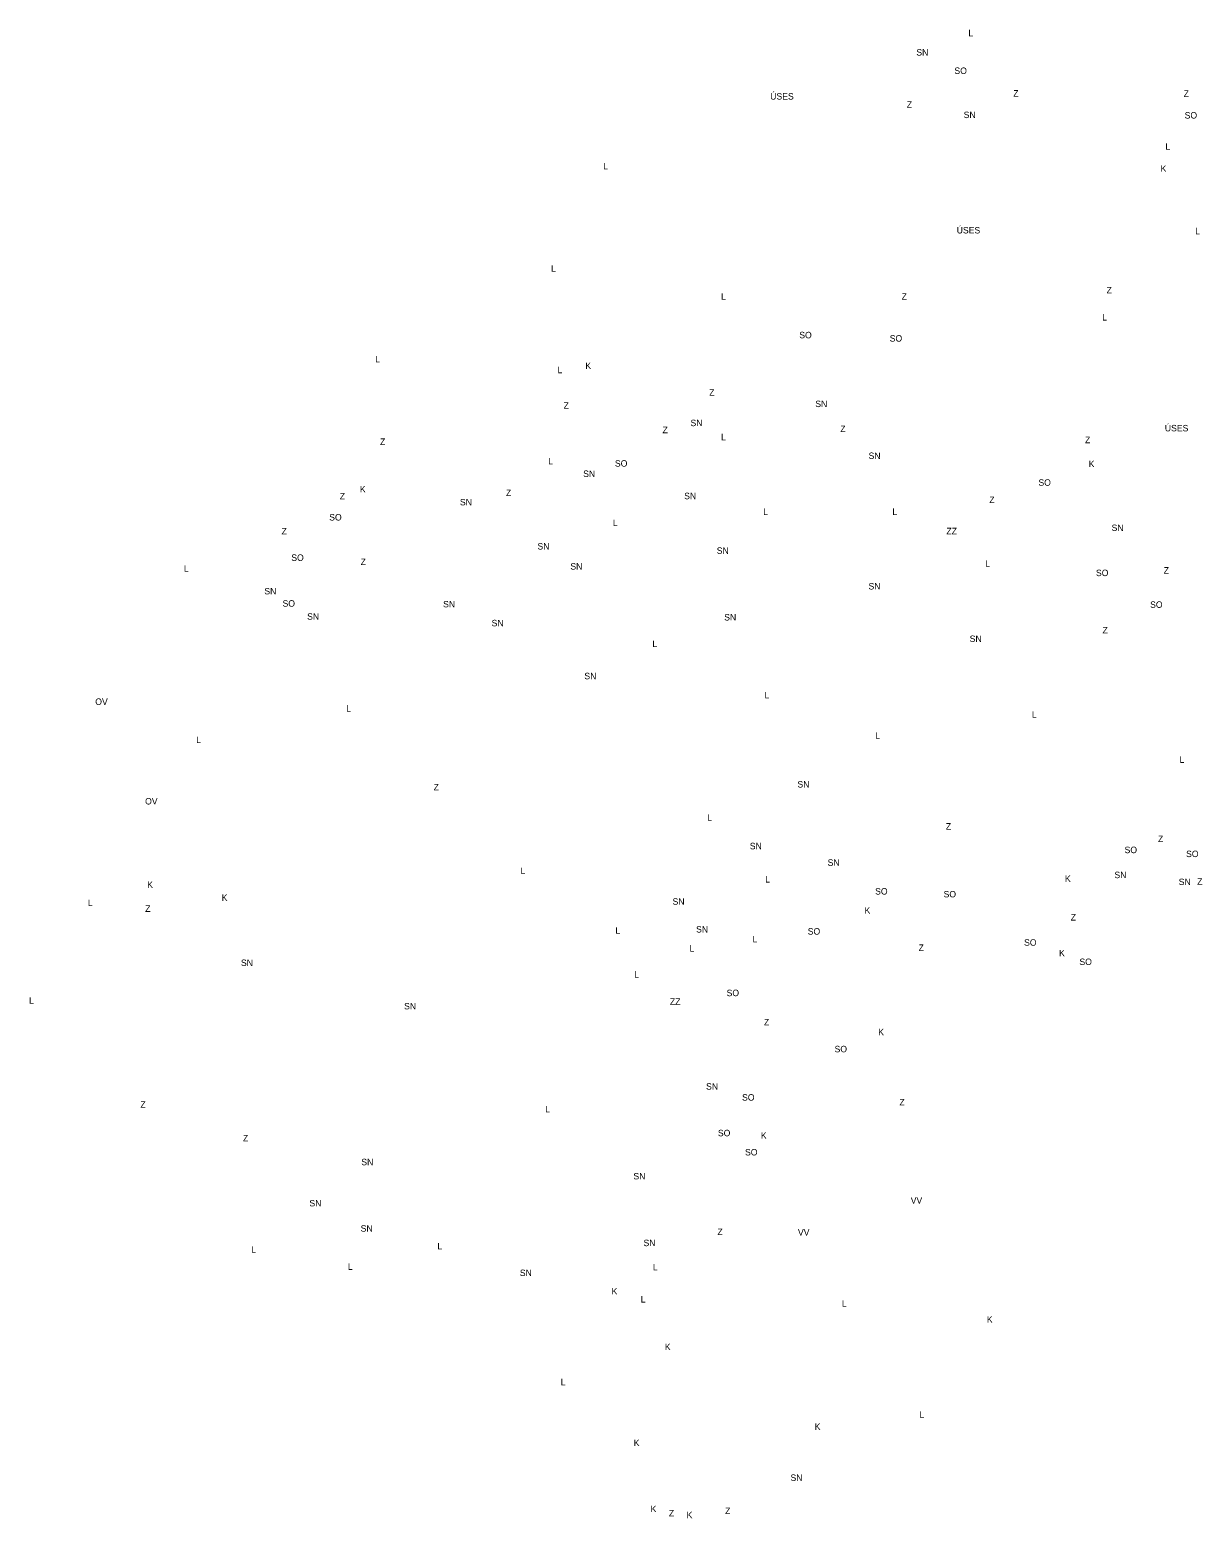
# Model space of a CAD drawing. Extents: x -445021 to -431236, y -1134464 to -1129615.
# Drawn here: x -445021 to -443206, y -1134464 to -1132160 of the extents above; entities that cross this region are included whole.
import ezdxf

# ---------------------------------------------------------------- set-up
doc = ezdxf.new("R2010")
doc.units = 0
doc.layers.add('Vrstva 84', color=7, linetype='Continuous')

msp = doc.modelspace()

# ---------------------------------------------------------------- texts
at = {"layer": 'Vrstva 84'}
for s, p in [('L', (-443568.4, -1132169.6)), ('SN', (-443649, -1132199.5)), ('SO', (-443590, -1132228)), ('ÚSES', (-443875.2, -1132267.6)), ('Z', (-443498.9, -1132263)), ('Z', (-443235.2, -1132263.5)), ('Z', (-443663.8, -1132280.3)), ('SN', (-443575.7, -1132296.3)), ('SO', (-443233.6, -1132297)), ('L', (-443263.4, -1132345.2)), ('L', (-444133.8, -1132375.8)), ('K', (-443270.8, -1132379.4)), ('ÚSES', (-443586.5, -1132474.9)), ('L', (-443217.3, -1132476.1)), ('L', (-444214.5, -1132534.2)), ('L', (-443951.2, -1132577.6)), ('Z', (-443671.7, -1132577.4)), ('Z', (-443354.5, -1132567.7)), ('L', (-443361.2, -1132609.7)), ('SO', (-443830.2, -1132637.2)), ('SO', (-443690.2, -1132642.3)), ('L', (-444486.6, -1132674.6)), ('L', (-444204.3, -1132691.2)), ('K', (-444161.4, -1132684.8)), ('Z', (-443969.6, -1132726)), ('Z', (-444195.1, -1132746.4)), ('SN', (-443805.4, -1132743.7)), ('SN', (-443998.6, -1132773.2)), ('Z', (-444041.9, -1132784.1)), ('L', (-443951.2, -1132795)), ('Z', (-443766.7, -1132782.3)), ('ÚSES', (-443264.3, -1132781.3)), ('Z', (-444479.2, -1132802.3)), ('Z', (-443387.9, -1132799.6)), ('L', (-444218.8, -1132832.4)), ('SO', (-444115.6, -1132835.9)), ('SN', (-443722.9, -1132824.1)), ('K', (-443382.1, -1132836.7)), ('SN', (-444164.8, -1132851.9)), ('SO', (-443460, -1132865.5)), ('Z', (-444541.6, -1132886.7)), ('K', (-444510.4, -1132875.8)), ('Z', (-444284.2, -1132881.3)), ('SN', (-444008.4, -1132886.3)), ('SN', (-444355.5, -1132895.9)), ('L', (-443886.1, -1132910.6)), ('L', (-443686, -1132910.6)), ('Z', (-443536, -1132892.3)), ('SO', (-444557.9, -1132919.3)), ('L', (-444118.7, -1132927.9)), ('Z', (-444631.7, -1132940.9)), ('ZZ', (-443602.4, -1132940.6)), ('SN', (-443346.7, -1132935.6)), ('SN', (-444235.5, -1132964.2)), ('SN', (-443958, -1132970.9)), ('L', (-444782.9, -1132998.7)), ('SO', (-444616.6, -1132981.8)), ('Z', (-444509.2, -1132988.2)), ('SN', (-444184.6, -1132995.3)), ('L', (-443542.4, -1132991)), ('Z', (-443266, -1133001.5)), ('SN', (-443723, -1133026.1)), ('SO', (-443370.9, -1133005.4)), ('SN', (-444658.3, -1133033.7)), ('SO', (-444630.2, -1133052.7)), ('SN', (-444592.1, -1133072.9)), ('SN', (-444381.6, -1133053.8)), ('SO', (-443287.1, -1133054.5)), ('SN', (-444306.5, -1133083.1)), ('SN', (-443946.4, -1133074.1)), ('Z', (-443360.7, -1133094.1)), ('L', (-444057.6, -1133115.3)), ('SN', (-443566.4, -1133107.4)), ('SN', (-444162.9, -1133165.1)), ('OV', (-444920.1, -1133204.8)), ('L', (-443884, -1133194.7)), ('L', (-444531.6, -1133215.1)), ('L', (-443470.1, -1133224.7)), ('L', (-443712.5, -1133257.3)), ('L', (-444763.8, -1133263.9)), ('L', (-443241.5, -1133294.5)), ('Z', (-444396.2, -1133337)), ('SN', (-443833.1, -1133332.7)), ('OV', (-444842.9, -1133358.9)), ('L', (-443972.6, -1133384.1)), ('Z', (-443603.2, -1133397.8)), ('Z', (-443274.9, -1133417.2)), ('SN', (-443906.8, -1133428.3)), ('SO', (-443326.6, -1133434.3)), ('SO', (-443231.4, -1133440.4)), ('SN', (-443786.3, -1133453.9)), ('K', (-444839.7, -1133488.1)), ('L', (-444261.8, -1133466.6)), ('L', (-443883, -1133479.8)), ('K', (-443418.9, -1133478.8)), ('SN', (-443342.3, -1133473)), ('SN', (-443242.8, -1133483.7)), ('Z', (-443214.2, -1133483.2)), ('K', (-444724.4, -1133508.2)), ('SO', (-443712.8, -1133498.4)), ('SO', (-443606.8, -1133502.8)), ('L', (-444931.4, -1133516.1)), ('Z', (-444842.8, -1133525.2)), ('SN', (-444026.4, -1133514.2)), ('K', (-443729.1, -1133528)), ('SN', (-443990, -1133557.2)), ('Z', (-443410, -1133538.6)), ('L', (-444114.9, -1133559)), ('L', (-443902.4, -1133572.5)), ('SO', (-443817.1, -1133560.4)), ('SO', (-443482.2, -1133577.6)), ('L', (-444000.1, -1133586.7)), ('Z', (-443645.5, -1133585.7)), ('K', (-443428, -1133594)), ('SN', (-444694.5, -1133609)), ('SO', (-443396.5, -1133607.5)), ('L', (-444085.6, -1133626.9)), ('L', (-445022.6, -1133667.3)), ('ZZ', (-444030.5, -1133669.2)), ('SO', (-443942.7, -1133655.7)), ('SN', (-444442, -1133676.2)), ('Z', (-443884.8, -1133700.8)), ('K', (-443708, -1133716.2)), ('SO', (-443775.6, -1133742.6)), ('SN', (-443974.5, -1133800.4)), ('Z', (-444850.2, -1133828.4)), ('SO', (-443918.8, -1133817.4)), ('Z', (-443675.2, -1133824.9)), ('L', (-444223.5, -1133835.6)), ('SO', (-443956.2, -1133872.6)), ('K', (-443889.6, -1133876.4)), ('Z', (-444691.4, -1133880.4)), ('SO', (-443914.2, -1133902.3)), ('SN', (-444508.2, -1133917.5)), ('SN', (-444087, -1133939.4)), ('SN', (-444588.6, -1133981.2)), ('VV', (-443657.7, -1133977)), ('SN', (-444509.2, -1134020.3)), ('Z', (-443957, -1134025.6)), ('VV', (-443832.3, -1134026.4)), ('L', (-444678.7, -1134052.9)), ('L', (-444390.5, -1134047.8)), ('SN', (-444071.3, -1134042.7)), ('L', (-444529, -1134079.4)), ('L', (-444056.8, -1134080.1)), ('SN', (-444262.8, -1134089)), ('K', (-444120.7, -1134117.5)), ('L', (-444075.7, -1134130)), ('L', (-443764.1, -1134136.6)), ('K', (-443539.8, -1134161.2)), ('K', (-444038.3, -1134203.6)), ('L', (-444199.6, -1134258.1)), ('L', (-443643.9, -1134308.7)), ('K', (-443806.4, -1134327.1)), ('K', (-444086.4, -1134352.3)), ('SN', (-443843.8, -1134406.2)), ('K', (-444060.3, -1134454.5)), ('Z', (-444032.1, -1134461.2)), ('K', (-444004.6, -1134463.9)), ('Z', (-443945.1, -1134457.6))]:
    msp.add_text(s, height=10, dxfattribs=at).set_placement(p)

doc.saveas('drawing.dxf')
